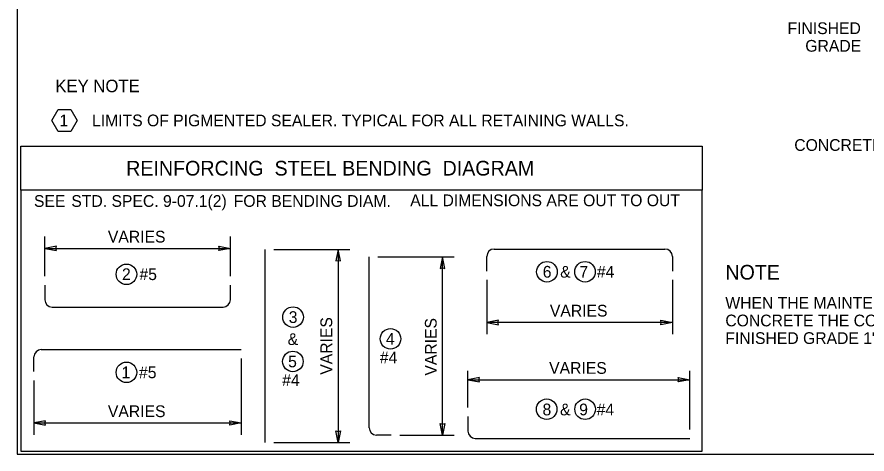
# Model space of a CAD drawing. Extents: x 99862 to 103680, y 99470 to 105076.
# Drawn here: x 99862 to 101020, y 100000 to 100595 of the extents above; entities that cross this region are included whole.
import ezdxf

# ---------------------------------------------------------------- set-up
doc = ezdxf.new("R2010")
doc.units = 0
for name, color, linetype in [('Level 1', 7, 'Continuous'), ('Level 10', 7, 'Continuous'), ('Level 15', 7, 'Continuous'), ('Level 20', 7, 'Continuous'), ('Level 40', 7, 'Continuous'), ('Level 60', 7, 'Continuous')]:
    doc.layers.add(name, color=color, linetype=linetype)

msp = doc.modelspace()

# ---------------------------------------------------------------- linework, layer by layer
at = {"layer": 'Level 1'}
msp.add_lwpolyline([(99862, 99999.5), (103151, 99999.5), (103151, 102075.5), (99862, 102075.5)], close=True, dxfattribs=at)
at = {"layer": 'Level 10'}
for p, q in [((100199.7, 100278.4), (100199.7, 100015.2)), ((100511.9, 100278.9), (100744.6, 100278.9)), ((100341.6, 100035.4), (100341.6, 100268.2)), ((100501.9, 100248.9), (100501.9, 100268.9)), ((100754.6, 100268.9), (100754.6, 100248.9)), ((99899.9, 100229.8), (99899.9, 100209.8)), ((100152.6, 100209.8), (100152.6, 100229.8)), ((99909.9, 100199.8), (100142.6, 100199.8)), ((99895.1, 100141.8), (100167.4, 100141.8)), ((99885.1, 100111.8), (99885.1, 100131.8)), ((100476.1, 100050.8), (100476.1, 100030.8)), ((100371.6, 100025.4), (100351.6, 100025.4)), ((100486.1, 100020.8), (100778.3, 100020.8))]:
    msp.add_line(p, q, dxfattribs=at)
for centre, start, end in [((100511.9, 100268.9), 90, 180), ((100744.6, 100268.9), 0, 90), ((99909.9, 100209.8), 180, 270), ((100142.6, 100209.8), 270, 0), ((99895.1, 100131.8), 90, 180), ((100351.6, 100035.4), 180, 270), ((100486.1, 100030.8), 180, 270)]:
    msp.add_arc(centre, 10, start, end, dxfattribs=at)
at = {"layer": 'Level 15'}
for p, q in [((99899.9, 100241.8), (99899.9, 100295.8)), ((100152.6, 100241.8), (100152.6, 100295.8)), ((99899.9, 100279.8), (100152.6, 100279.8)), ((100211.7, 100278.4), (100315.3, 100278.4)), ((100299.3, 100278.4), (100299.3, 100015.2)), ((100353.6, 100268.2), (100457.6, 100268.2)), ((100441.6, 100025.4), (100441.6, 100268.2)), ((100501.9, 100236.9), (100501.9, 100162.9)), ((100754.6, 100236.9), (100754.6, 100162.9)), ((100754.6, 100178.9), (100501.9, 100178.9)), ((100167.4, 100129.8), (100167.4, 100025.8)), ((100476.1, 100062.8), (100476.1, 100112.8)), ((100778.3, 100032.8), (100778.3, 100112.8)), ((99885.1, 100099.8), (99885.1, 100025.8)), ((100476.1, 100100.8), (100778.3, 100100.8)), ((99885.1, 100041.8), (100167.4, 100041.8)), ((100383.6, 100025.4), (100457.6, 100025.4)), ((100211.7, 100015.2), (100315.3, 100015.2))]:
    msp.add_line(p, q, dxfattribs=at)
for points in [[(99899.9, 100279.8), (99915.6, 100276.7), (99914.9, 100279.8), (99915.6, 100282.9)], [(100152.6, 100279.8), (100136.9, 100276.7), (100137.6, 100279.8), (100136.9, 100282.9)], [(100299.3, 100278.4), (100296.2, 100262.7), (100299.3, 100263.4), (100302.4, 100262.7)], [(100441.6, 100268.2), (100438.5, 100252.5), (100441.6, 100253.2), (100444.7, 100252.5)], [(100501.9, 100178.9), (100517.6, 100175.8), (100516.9, 100178.9), (100517.6, 100182)], [(100754.6, 100178.9), (100738.9, 100175.8), (100739.6, 100178.9), (100738.9, 100182)], [(100476.1, 100100.8), (100491.8, 100097.7), (100491.1, 100100.8), (100491.8, 100103.9)], [(100778.3, 100100.8), (100762.6, 100097.7), (100763.3, 100100.8), (100762.6, 100103.9)], [(99885.1, 100041.8), (99900.9, 100038.7), (99900.1, 100041.8), (99900.9, 100044.9)], [(100167.4, 100041.8), (100151.7, 100038.7), (100152.4, 100041.8), (100151.7, 100044.9)], [(100441.6, 100025.4), (100438.5, 100041.2), (100441.6, 100040.4), (100444.7, 100041.2)], [(100299.3, 100015.2), (100296.2, 100030.9), (100299.3, 100030.2), (100302.4, 100030.9)]]:
    msp.add_lwpolyline(points, close=True, dxfattribs=at)
at = {"layer": 'Level 20'}
msp.add_lwpolyline([(99909.5, 100454.2), (99918.2, 100469.2), (99935.5, 100469.2), (99944.1, 100454.2), (99935.5, 100439.2), (99918.2, 100439.2), (99909.5, 100454.2)], dxfattribs=at)
for centre in [(100583.8, 100247.9), (100635.7, 100247.9), (100011.1, 100244.5), (100238, 100186.1), (100370.7, 100156.5), (100237.8, 100125.7), (100011.1, 100110.8), (100583.5, 100060.6), (100635.8, 100060.5)]:
    msp.add_circle(centre, 14, dxfattribs=at)
at = {"layer": 'Level 40'}
for points in [[(99867.4, 100419.1), (100795.3, 100419.1), (100795.3, 100359.1), (99867.4, 100359.1)], [(99867.4, 100003.4), (100795.3, 100003.4), (100795.3, 100359.1), (99867.4, 100359.1)]]:
    msp.add_lwpolyline(points, close=True, dxfattribs=at)
at = {"layer": 'Level 60'}
msp.add_line((99862, 99999.5), (99862, 99999.5), dxfattribs=at)

# ---------------------------------------------------------------- texts
at = {"layer": 'Level 20'}
for s, height, p in [('FINISHED', 16, (100911.5, 100571.9)), ('GRADE', 16, (100935.7, 100547.9)), ('KEY NOTE', 17, (99914.2, 100492.7)), ('1', 16, (99919.9, 100446.2)), ('LIMITS OF PIGMENTED SEALER. TYPICAL FOR ALL RETAINING WALLS.', 16, (99964.2, 100446.2)), ('CONCRETE MAINTENANCE ', 16, (100920.7, 100412.7)), ('REINFORCING  STEEL BENDING  DIAGRAM', 20, (100010.7, 100379.1)), ('SEE ', 16, (99885.1, 100336.4)), ('STD. SPEC. 9-07.1(2)', 16, (99936, 100336.4)), ('FOR BENDING DIAM.', 16, (100157.2, 100336.4)), ('ALL DIMENSIONS ARE OUT TO OUT', 16, (100397.6, 100337.3)), ('VARIES', 16, (99985.8, 100287.8)), ('2  #5', 16, (100005, 100236.6)), ('6  &  7  #4', 16, (100578.1, 100239.9)), ('NOTE', 20, (100826.8, 100237.3)), ('WHEN THE MAINTENANCE PAD ABUTS ASPHALT OR ', 16, (100826.8, 100197.5)), ('VARIES', 16, (100587.8, 100186.9)), ('3', 16, (100232.1, 100178.1)), ('CONCRETE THE CONTRACTOR SHALL MODIFY THE ', 16, (100826.8, 100173.5)), ('&', 16, (100230.6, 100148.1)), ('4', 16, (100364.5, 100148.5)), ('FINISHED GRADE 1" (IN) MINIMUM TO 2" (IN) MAXIMUM.', 16, (100826.8, 100149.5)), ('5', 16, (100231.3, 100117.7)), ('#4', 16, (100356.2, 100123)), ('VARIES', 16, (100586.8, 100108.8)), ('1  #5', 16, (100004.4, 100102.8)), ('#4', 16, (100223.2, 100092.3)), ('VARIES', 16, (99985.8, 100049.8)), ('8  &  9  #4', 16, (100577.8, 100052.2))]:
    msp.add_text(s, height=height, dxfattribs=at).set_placement(p)
for p in [(100291.3, 100107.6), (100433.6, 100106.4)]:
    msp.add_text('VARIES', height=16, rotation=90, dxfattribs=at).set_placement(p)

doc.saveas('drawing.dxf')
